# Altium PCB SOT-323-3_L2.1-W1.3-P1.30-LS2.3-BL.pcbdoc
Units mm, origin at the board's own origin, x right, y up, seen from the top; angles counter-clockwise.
Board outline 15.03 x 15.52 mm, 2 copper layers (Top Layer, Bottom Layer), stack 0 mm thick; 1 components, 0 nets, 3 pads, 0 vias.
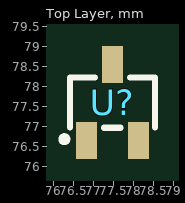
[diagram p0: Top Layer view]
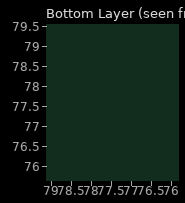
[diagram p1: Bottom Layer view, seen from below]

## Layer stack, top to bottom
Top Layer: signal copper (thickness not stored)
Bottom Layer: signal copper (thickness not stored)

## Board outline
84.885,69.85 69.85,69.85 69.85,85.369 84.885,85.369

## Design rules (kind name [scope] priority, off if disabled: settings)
PasteMaskExpansion "Paste Mask Expansion" [All] p1: expansion=0
SolderMaskExpansion "Solder Mask Expansion" [IsVia] p1: expansion=-25.4 istentingtop=TRUE
SolderMaskExpansion "Solder Mask Expansion" [All] p2: expansion=0.051 istentingtop=FALSE

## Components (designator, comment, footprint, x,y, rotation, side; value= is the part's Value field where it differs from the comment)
U? "" SOT-323-3_L2.1-W1.3-P1.30-LS2.3-BL 77.475,77.609 r0 top

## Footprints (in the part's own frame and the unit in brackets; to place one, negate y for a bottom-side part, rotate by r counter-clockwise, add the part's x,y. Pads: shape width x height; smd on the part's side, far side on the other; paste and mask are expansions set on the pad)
SOT-323-3_L2.1-W1.3-P1.30-LS2.3-BL [mm]
  rect 0.525x0.919 smd: 1(-0.65,-0.95) 2(0.65,-0.95) 3(0,0.95)
  silkscreen extent -1.27,-0.99 1.06,0.62

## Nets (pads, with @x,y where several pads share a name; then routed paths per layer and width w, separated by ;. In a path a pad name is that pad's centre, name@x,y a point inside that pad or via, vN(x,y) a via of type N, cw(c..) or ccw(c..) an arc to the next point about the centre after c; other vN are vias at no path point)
pads on no net: U?.1 U?.2 U?.3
